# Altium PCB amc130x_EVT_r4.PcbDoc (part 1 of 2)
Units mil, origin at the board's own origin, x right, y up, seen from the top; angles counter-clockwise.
Board outline 4400 x 2100 mil, 2 copper layers (Top Layer, Bottom Layer), stack 62 mil thick; 70 components, 42 nets, 166 pads, 13 vias.
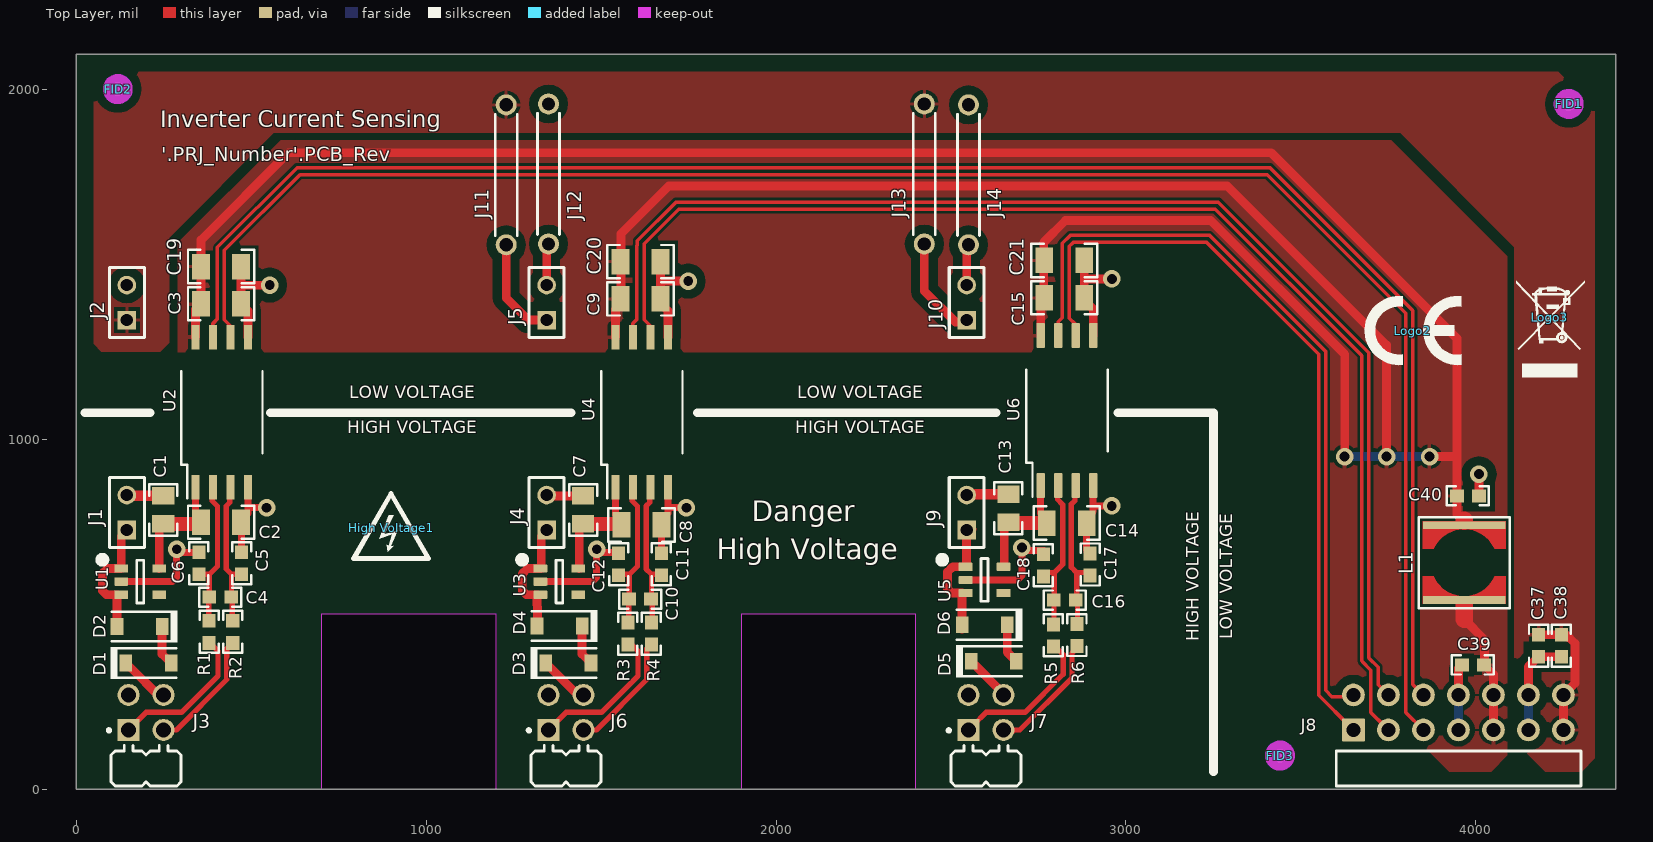
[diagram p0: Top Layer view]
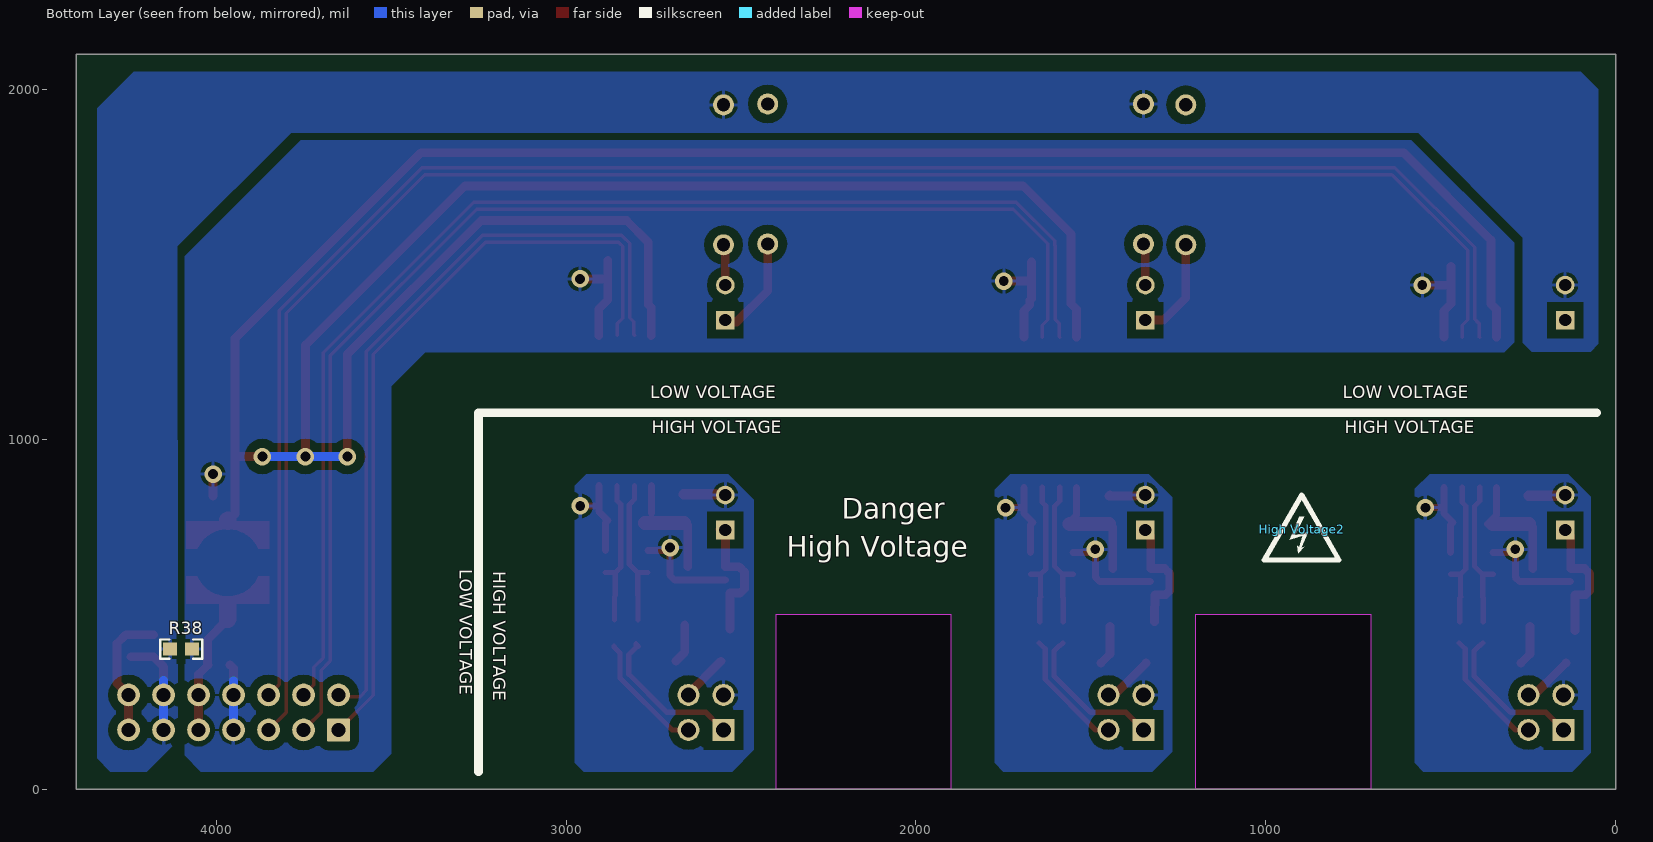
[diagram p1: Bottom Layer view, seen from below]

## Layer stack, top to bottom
Top Solder: solder mask 0.4, Solder Resist, Dk 3.5
Top Layer: signal copper 1.4
Dielectric1: core 59.2, FR-4, Dk 4.8
Bottom Layer: signal copper 1.4
Bottom Solder: solder mask 0.4, Solder Resist, Dk 3.5

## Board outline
0,0 0,2100 4400,2100 4400,0
cut-out: 1900,500 1900,0 2400,0 2400,500
cut-out: 700,500 700,0 1200,0 1200,500

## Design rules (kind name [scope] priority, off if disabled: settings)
AcuteAngle [All] p1: minimum=4.50000000000000E+0001 checktracksonly=FALSE
AssemblyTestPointUsage [All] p1: valid=2
BoardOutlineClearance BoardOutlineClearance_MountingHoles [OnCopper and InComponentClass('Mounting Holes')] p1: gap=39.37 ignorepadtopadclearanceinfootprint=FALSE
BoardOutlineClearance BoardOutlineClearance_Poly [OnCopper and IsPoly] p2: gap=25 ignorepadtopadclearanceinfootprint=FALSE
BoardOutlineClearance [OnCopper and Not InComponentClass('Logo') and not InComponentClass('FiducialMark') and not InRegion(1000,500,4000,800) and not InPoly and Not IsKeepOut] p3: gap=60 ignorepadtopadclearanceinfootprint=FALSE except(25: Poly-CutoutEdge Text-CutoutEdge; 50: Arc-CutoutEdge Track-CutoutEdge SMDPad-CutoutEdge THPad-CutoutEdge Via-CutoutEdge Fill-CutoutEdge Region-CutoutEdge)
Clearance Clearance_Keepouts [((IsTrack Or IsArc) And Not InPoly) And IsFree and IsKeepOut vs ((IsTrack Or IsArc) And Not InPoly) And IsFree and IsKeepOut] p1: gap=0 ignorepadtopadclearanceinfootprint=FALSE
Clearance Clearance_Small_Vias [(HoleDiameter = 10)] p2: gap=8 ignorepadtopadclearanceinfootprint=TRUE
Clearance Clearance_TP_blue_wires [HasFootprint('TP_H045P075')] p3: gap=15 ignorepadtopadclearanceinfootprint=TRUE
Clearance Clearance_3V3 [InNet('3V3')] p4: gap=15 ignorepadtopadclearanceinfootprint=TRUE
Clearance Clearance_10_mil_traces [Width = 10] p5: gap=8 ignorepadtopadclearanceinfootprint=TRUE
Clearance Clearance_Poly [InPolygon] p6: gap=25 ignorepadtopadclearanceinfootprint=TRUE except(10: Fill-Fill Fill-Poly Fill-Region Poly-Poly Poly-Region Region-Region)
Clearance Clearance_FiducialMark [IsKeepOut and InComponentClass('FiducialMark') vs IsPad and InComponentClass('FiducialMark')] p7: gap=0 ignorepadtopadclearanceinfootprint=FALSE
Clearance [All] p8: gap=7.87 ignorepadtopadclearanceinfootprint=TRUE
ComponentClearance ComponentClearance_MountingHoles_FiducialMarks [InComponentClass('Mounting Holes') vs InComponentClass('FiducialMark')] p1: gap=50 collisioncheckmode=3 verticalgap=10 showdistances=FALSE
ComponentClearance ComponentClearance_Shunt [InComponentClass('Header') vs InComponentClass('Shunt')] p2: gap=0 collisioncheckmode=3 verticalgap=0 showdistances=FALSE
ComponentClearance ComponentClearance_Logo [InComponentClass('Logo')] p3: gap=50 collisioncheckmode=3 verticalgap=10 showdistances=FALSE
ComponentClearance ComponentClearance_ScrewToNut [(HasFootprint('NY PMS 440 0025 PH')) vs (HasFootprint('Keystone_1902C'))] p4: gap=5 collisioncheckmode=3 verticalgap=10 showdistances=FALSE
ComponentClearance ComponentClearance_MountingHoles [InComponentClass('Mounting Holes')] p5: gap=250 collisioncheckmode=3 verticalgap=100000 showdistances=FALSE
ComponentClearance ComponentClearance_SmallPassives [HasFootprint('0201*') or HasFootprint('0402*') or HasFootprint('0508') or HasFootprint('0603*') or HasFootprint('0612') or HasFootprint('0805*') or HasFootprint('0815*') or HasFootprint('0830*') or HasFootprint('1206*') or HasFootprint('1210*') or HasFootprint('1808*') or HasFootprint('1812*') or HasFootprint('1825*') or HasFootprint('2010*') or HasFootprint('2220*') or HasFootprint('2225*') or HasFootprint('2512*') or HasFootprint('2728*') or HasFootprint('3518*') vs HasFootprint('0201*') or HasFootprint('0402*') or HasFootprint('0508') or HasFootprint('0603*') or HasFootprint('0612') or HasFootprint('0805*') or HasFootprint('0815*') or HasFootprint('0830*') or HasFootprint('1206*') or HasFootprint('1210*') or HasFootprint('1808*') or HasFootprint('1812*') or HasFootprint('1825*') or HasFootprint('2010*') or HasFootprint('2220*') or HasFootprint('2225*') or HasFootprint('2512*') or HasFootprint('2728*') or HasFootprint('3518*')] p6: gap=14.96 collisioncheckmode=3 verticalgap=10 showdistances=FALSE
ComponentClearance ComponentClearance_THtoSMT [IsThruComponent vs IsSMTComponent] p7: gap=20 collisioncheckmode=3 verticalgap=30 showdistances=FALSE
ComponentClearance ComponentClearance_TestPoint [HasFootprint('TP_H045P075')] p8: gap=0 collisioncheckmode=3 verticalgap=30 showdistances=FALSE
ComponentClearance ComponentClearance_THtoTH [IsThruComponent vs IsThruComponent] p9: gap=30 collisioncheckmode=3 verticalgap=30 showdistances=FALSE
ComponentClearance [All] p10: gap=30 collisioncheckmode=3 verticalgap=10 showdistances=FALSE
DiffPairsRouting [All] p1: maxlimit=100 minlimit=10 mostfreqgap=10 toplayer_minwidth=10 toplayer_maxwidth=15 toplayer_prefwidth=10 bottomlayer_minwidth=10 bottomlayer_maxwidth=15 bottomlayer_prefwidth=10 maxuncoupledlength=1000
FabricationTestPointUsage TestPointUsage [All] p1: valid=2 allowmultiple=FALSE
FabricationTestpoint Testpoint [All] p1: side=3 testpointundercomponent=TRUE minsize=40 maxsize=100 preferedsize=60 minholesize=0 maxholesize=40 preferedholesize=32 testpointgrid=1 allowsidetop=TRUE allowsidebottom=TRUE usegrid=TRUE gridtolerance=0.01
FanoutControl Fanout_LCC [IsLCC] p1: bgadir=Out bgaviamode=Centered fanoutstyle=Auto fanoutdirection=Alternating viagrid=1 // Fanout_LCC (Default Rule)
FanoutControl Fanout_BGA [IsBGA] p2: bgadir=Out bgaviamode=Centered fanoutstyle=Auto fanoutdirection=Alternating viagrid=1 // Fanout_BGA (Default Rule)
FanoutControl Fanout_Default [All] p4: bgadir=Out bgaviamode=Centered fanoutstyle=Auto fanoutdirection=Alternating viagrid=1 // Fanout_Default (Default Rule)
FanoutControl Fanout_Small [(CompPinCount < 5)] p5: bgadir=Out bgaviamode=Centered fanoutstyle=Auto fanoutdirection=OutThenIn viagrid=1 // Fanout_Small (Default Rule)
HoleSize [All] p1: absolutevalues=TRUE maxlimit=251 minlimit=7.87 maxpercent=80.000 minpercent=20.000
MinimumAnnularRing MinimumAnnularRing_ThermalPadVias [IsVia and InAnyComponent] p1: minimumring=5.91
MinimumAnnularRing [All] p2: minimumring=6
MinimumSolderMaskSliver MinimumSolderMaskSliver_Logo [InComponentClass('Logo') vs InComponentClass('Logo')] p1: minsoldermaskwidth=0.7
MinimumSolderMaskSliver [All] p2: minsoldermaskwidth=3.94
PlaneConnect [All] p1: planeconnectstyle=Relief reliefexpansion=10 reliefentries=4 reliefconductorwidth=10 reliefairgap=10
PolygonConnect [All] p1: connectstyle=Relief reliefconductorwidth=10 reliefentries=4 polygonreliefangle="90 Angle" airgapwidth=10
RoomDefinition Hardware [InComponentClass('Hardware')] p1: confinementstyle=ConfineIn formatcopy=TRUE lockcomponents=FALSE outline 8,-284 608,-284 608,1566 8,1566
RoutingVias ThermalPadVias [IsVia and InAnyComponent] p1: holewidth=7.87 width=19.68 viastyle="Through Hole" minholewidth=7.87 minwidth=19.68 maxholewidth=12.99 maxwidth=23.62
RoutingVias [All] p2: holewidth=16 width=34 viastyle="Through Hole" minholewidth=7.87 minwidth=22 maxholewidth=40 maxwidth=65
SilkToBoardRegionClearance [Not ((IsComment or IsDesignator) And (Hide <> 'False')) and not InRegion(1000,500,4000,800)] p1:
SilkToSilkClearance SilkToSilkClearance_Pb-FreeLogo [(HasFootprint('Pb-Free_Overlay_Medium') OR HasFootprint('Pb-Free_Overlay_Small')) vs (HasFootprint('Pb-Free_Overlay_Medium') OR HasFootprint('Pb-Free_Overlay_Small'))] p1: silktosilkclearance=0
SilkToSilkClearance [All] p2: silktosilkclearance=3.94
SilkToSolderMaskClearance SilkToComponentPadClearance [(IsPad or IsFill or IsRegion) and InAnycomponent] p1: minsilkscreentomaskgap=5 clearancetoexposedcopper=TRUE
SilkToSolderMaskClearance "Silk to Solder Mask Opening" [All] p2: minsilkscreentomaskgap=3 clearancetoexposedcopper=FALSE
SolderMaskExpansion [All] p1: expansion=1.97
UnRoutedNet [All] p1: checkbadconnections=TRUE
Width [All] p1: maxlimit=100 minlimit=6 preferedwidth=10 checkconnectedcopper=TRUE
14 further rules are at their usual default settings.

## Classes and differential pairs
component class FiducialMark: FID1 FID2 FID3
component class AssemblyNote: ZZ1 ZZ2 ZZ3 ZZ4
component class Header: J3 J6 J7 J8
differential pair Ics: +Ics_P -Ics_N
differential pair Ibs: +Ibs_P -Ibs_N
differential pair Ias: +Ias_P -Ias_N
differential pair Ic: +Ic_P -Ic_N
differential pair Ib: +Ib_P -Ib_N
differential pair Ia: +Ia_P -Ia_N

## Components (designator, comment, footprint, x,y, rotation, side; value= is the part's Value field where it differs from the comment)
C1 "GRM21BR70J106KE76L" 0805_HV 249.02,797.47 r270 top value=10uF
C2 "1206YC104KAT2A" 1206 414.24,762.33 r0 top value=0.1uF
C3 "1206YC104KAT2A" 1206 414.24,1386.56 r180 top value=0.1uF
C4 "06035A331JAT2A" 0603 411.82,548.34 r0 top value=330pF
C5 "06035A100JAT2A" 0603 472.85,644.98 r90 top value=10pF
C6 "06035A100JAT2A" 0603 350.66,644.98 r90 top value=10pF
C7 "GRM21BR70J106KE76L" 0805_HV 1449.02,797.47 r270 top value=10uF
C8 "1206YC104KAT2A" 1206 1615.76,754.71 r0 top value=0.1uF
C9 "1206YC104KAT2A" 1206 1612.73,1400.73 r180 top value=0.1uF
C10 "06035A331JAT2A" 0603 1611.49,542.39 r0 top value=330pF
C11 "06035A100JAT2A" 0603 1672.51,642.39 r90 top value=10pF
C12 "06035A100JAT2A" 0603 1550.46,642.39 r90 top value=10pF
C13 "GRM21BR70J106KE76L" 0805_HV 2664.02,802.47 r270 top value=10uF
C14 "1206YC104KAT2A" 1206 2830.76,759.71 r0 top value=0.1uF
C15 "1206YC104KAT2A" 1206 2823.69,1403.68 r180 top value=0.1uF
C16 "06035A331JAT2A" 0603 2824.95,540 r0 top value=330pF
C17 "06035A100JAT2A" 0603 2897.69,641.5 r90 top value=10pF
C18 "06035A100JAT2A" 0603 2764.1,639.04 r90 top value=10pF
C19 "GRM31MR71C225KA35L" 1206 414.24,1493.02 r180 top value=2.2uF
C20 "GRM31MR71C225KA35L" 1206 1612.73,1506.79 r180 top value=2.2uF
C21 "GRM31MR71C225KA35L" 1206 2823.69,1510.24 r180 top value=2.2uF
C37 "CGJ3E2X7R1C104K080AA" 0603 4178.99,409.45 r90 top value=0.1uF
C38 "GRM188R61C106KAALD" 0603 4243.99,409.45 r90 top value=10uF
C39 "CGJ3E2X7R1C104K080AA" 0603 3991.39,354.47 r0 top value=0.1uF
C40 "GRM188R61C106KAALD" 0603 3977.12,837.47 r180 top value=10uF
D1 "MMSZ4687-HE3-08" SOD-123 206.91,360 r0 top value=4.3V
D2 "MMSZ4687-HE3-08" SOD-123 181.22,464.58 r180 top value=4.3V
D3 "MMSZ4687-HE3-08" SOD-123 1406.82,360 r0 top value=4.3V
D4 "MMSZ4687-HE3-08" SOD-123 1381.41,465.71 r180 top value=4.3V
D5 "MMSZ4687-HE3-08" SOD-123 2621.91,365 r0 top value=4.3V
D6 "MMSZ4687-HE3-08" SOD-123 2596.22,469.58 r180 top value=4.3V
FID1 "Fiducial" Fiducial10-20 4265,1957.5 r0 top
FID2 "Fiducial" Fiducial10-20 118.99,2000 r0 top
FID3 "Fiducial" Fiducial10-20 3440,95.47 r0 top
"High Voltage1" "DANGER HIGH VOLTAGE" IEC_HighVoltage_Small 900,746.58 r0 top
"High Voltage2" "DANGER HIGH VOLTAGE" IEC_HighVoltage_Small 898,742.64 r180 bottom
J1 "5-534206-1" CONN_534206-1 145,790 r90 top
J2 "5-534206-1" CONN_534206-1 145,1390 r90 top
J3 "PBC02DBAN" Sullins_PxC02DBAN 200,218.78 r90 top
J4 "5-534206-1" CONN_534206-1 1344.63,790 r90 top
J5 "5-534206-1" CONN_534206-1 1344.63,1390 r90 top
J6 "PBC02DBAN" Sullins_PxC02DBAN 1400,218.78 r90 top
J7 "PBC02DBAN" Sullins_PxC02DBAN 2600,218.78 r90 top
J8 "TSW-107-08-G-D-RA" TSW-107-08-G-D-RA 3950,218.78 r0 top
J9 "5-534206-1" CONN_534206-1 2545,790 r90 top
J10 "5-534206-1" CONN_534206-1 2545,1390 r90 top
J11 "923345-04-C" 3M_923345-04-C 1229.02,1755 r90 top
J12 "923345-04-C" 3M_923345-04-C 1350.04,1757.5 r90 top
J13 "923345-04-C" 3M_923345-04-C 2423.85,1757.5 r90 top
J14 "923345-04-C" 3M_923345-04-C 2550,1755 r90 top
L1 "MSS6122-104MLB" MSS6122 3966.43,646.79 r90 top value=100uH
Logo2 "CE Mark" CE_Mark_5mm 3820,1310 r0 top
Logo3 "WEEE logo" WEEE_Minimum 4211.13,1348.19 r0 top
R1 "MCR03EZPJ000" 0603 380.36,449.06 r90 top value=0
R2 "MCR03EZPJ000" 0603 447.62,449.06 r90 top value=0
R3 "MCR03EZPJ000" 0603 1576.56,444.06 r90 top value=0
R4 "MCR03EZPJ000" 0603 1643.73,444.06 r90 top value=0
R5 "MCR03EZPJ000" 0603 2792.64,438.94 r90 top value=0
R6 "MCR03EZPJ000" 0603 2860,439.98 r90 top value=0
R38 "ERJ-3GEY0R00V" 0603 4100,400 r180 bottom value=0
U1 "TPS76350DBVT" DBV0005A_N 183.33,592.6 r0 top
U2 "AMC1301DWVR" DWV0008A 416.45,1076.56 r90 top
U3 "TPS76350DBVT" DBV0005A_N 1380.87,592.6 r0 top
U4 "AMC1301DWVR" DWV0008A 1616.45,1076.56 r90 top
U5 "TPS76350DBVT" DBV0005A_N 2595.87,597.4 r0 top
U6 "AMC1301DWVR" DWV0008A 2831.45,1081.56 r90 top
ZZ1 "This Assembly Note is for PCB labels only" AssemblyNoteLabel 5384,3683 r180 top
ZZ2 "These assemblies are ESD sensitive, ESD precautions shall be observed." AssemblyNote 2884,3483 r180 top
ZZ3 "These assemblies must be clean and free from flux and all contaminants. Use of no clean flux is not acceptable." AssemblyNote 4459,3308 r180 top
ZZ4 "These assemblies must comply with workmanship standards IPC-A-610 Class 2, unless otherwise specified." AssemblyNote 4134,3133 r180 top

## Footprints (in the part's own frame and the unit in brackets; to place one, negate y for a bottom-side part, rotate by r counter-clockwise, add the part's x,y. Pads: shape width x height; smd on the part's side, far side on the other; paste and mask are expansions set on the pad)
3M_923345-04-C [mil] "Jumper Wire, 400 mil Spacing, Yellow, Pkg of 200"
  round 60 hole 38: 1(-200,0) 2(200,0)
  silkscreen extent -173,-31 173,31, body extent -215,-30 215,30, height 80
0603 [mm] "0603 from SM-752 data"
  rect 1x0.95 smd: 1(-0.8,0) 2(0.8,0)
  silkscreen extent -1.52,-0.69 1.52,0.69, body extent -0.87,-0.47 0.87,0.47, height 1
0805_HV [mil] "0805 with 30mil clearance between pads"
  rect 50x63 smd: 1(-40,0) 2(40,0)
  silkscreen extent -74,-40 74,40, body extent -43,-29 43,29, height 57
1206 [mm] "1206 from SM-752 data"
  rect 1.3x1.85 smd: 1(-1.45,0) 2(1.45,0)
  silkscreen extent -2.4,-1.21 2.4,1.21, body extent -1.7,-0.9 1.7,0.9, height 1.35
AssemblyNote [mil] "Assembly Note"
AssemblyNoteLabel [mil] "Assembly Note for PCB Labels"
CE_Mark_5mm [mil] "Minimum text height for CE Mark"
  silkscreen extent -138,-98 138,98
CONN_534206-1 [mm] "TE_CONNECTIVITY"
  rect 1.35x1.35 hole 0.89: 1(-1.27,0)
  round 1.35 hole 0.89: 2(1.27,0)
  silkscreen extent -3.68,-1.27 2.54,2.03, body extent -2.51,-1.27 2.51,1.27, height 8.65
DBV0005A_N [mm] "SOT23, 5-Leads, Body 2.9x1.6mm, Pitch 0.95mm, Lead Span 2.8mm, IPC Medium Density"
  rrect17% 1x0.6 smd: 1(-1.375,0.95) 2(-1.375,0) 3(-1.375,-0.95) 4(1.375,-0.95) 5(1.375,0.95)
  silkscreen extent -0.25,-1.55 0.25,1.55, body extent -1.42,-1.46 1.42,1.46, height 1.09
DWV0008A [mm] "SOIC, 8-Leads, Body 5.95x7.6mm (max), Pitch 1.27mm"
  rrect17% 1.8x0.6 smd: 1(-5.45,1.905) 2(-5.45,0.635) 3(-5.45,-0.635) 4(-5.45,-1.905) 5(5.45,-1.905) 6(5.45,-0.635) 7(5.45,0.635) 8(5.45,1.905)
  silkscreen extent -6.25,-2.95 2.98,2.95, body extent -5.77,-2.92 5.77,2.93, height 2.67
Fiducial10-20 [mm]
  round 1 smd mask+0.5: 1(0,0)
  Top Layer keep-out circle w1.178: c0,0 r0.5
IEC_HighVoltage_Small [mil]
  silkscreen extent -107,-88 107,97
MSS6122 [mm] "Coilcraft recommended land pattern Document 640-1 Revised 04/16/10"
  rect 0.575x6 smd: 1(-2.712,0) 2(2.712,0)
  Top Layer region: 1,-3 1,-2.209 1.874,-1.539 2.362,-0.551 2.362,0.551 1.874,1.539 1,2.209 1,2.209 1,3 3,3 3,-3
  Top Layer region: -3,-3 -1,-3 -1,-2.209 -1.874,-1.539 -2.362,-0.551 -2.362,0.551 -1.874,1.539 -1,2.209 -1,2.209 -1,3 -3,3
  silkscreen extent -3.3,-3.3 3.3,3.3, body extent -2.97,-3 3,3, height 2.22
SOD-123 [mm] "On Semi recommended land pattern"
  rect 0.915x1.22 smd: 1(-1.637,0) 2(1.637,0)
  silkscreen extent -2.74,-1.17 2.03,1.17, body extent -1.93,-0.9 1.93,0.9, height 1.35
Sullins_PxC02DBAN [mm] "Header, 2.54mm, 2x2, R/A, TH"
  rect 1.6x1.6 hole 1.1: 1(-1.27,1.27)
  round 1.6 hole 1.1: 2(1.27,1.27) 3(-1.27,-1.27) 4(1.27,-1.27)
  silkscreen extent -5.33,-2.54 -1.2,2.8, body extent -11.17,-2.54 1.59,2.54, height 5.08
TSW-107-08-G-D-RA [mm] "Samtec Right Angle Header"
  rrect6% 1.65x1.65 hole 1: 1(-7.62,-1.27)
  round 1.65 hole 1: 2(-7.62,1.27) 3(-5.08,-1.27) 4(-5.08,1.27) 5(-2.54,-1.27) 6(-2.54,1.27) 7(0,-1.27) 8(0,1.27) 9(2.54,-1.27) 10(2.54,1.27) 11(5.08,-1.27) 12(5.08,1.27) 13(7.62,-1.27) 14(7.62,1.27)
  silkscreen extent -8.87,-5.33 8.89,-2.79, body extent -8.89,-11.18 8.89,1.59, height 5.56
WEEE_Minimum [mil] "WEEElie bin"
  silkscreen extent -95,-172 99,104

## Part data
C1 C7 C13: library part CMP-0008311-2, "CAP, CERM, 10 uF, 6.3 V, +/- 10%, X7R, 0805", Cap_Case=0805, Manufacturer=MuRata, Supplier Part Number 1=490-3904-1-ND, TempCo=X7R, Tolerance_%=10%, Value1=Unknown, Value2=6.3V, ValueDisplayed=10uF
C2 C3 C8 C9 C14 C15: library part CMP-0860522-1, "CAP, CERM, 0.1 µF, 16 V,+/- 10%, X7R, 1206", Cap_Case=1206, Manufacturer=AVX, TempCo=X7R, Tolerance_%=10%, Value2=16V, ValueDisplayed=0.1µF
C4 C10 C16: library part CMP-0006784-4, "CAP, CERM, 330 pF, 50 V, +/- 5%, C0G/NP0, 0603", Cap_Case=0603, Manufacturer=AVX, Supplier Part Number 1=478-1181-1-ND, TempCo=C0G/NP0, Tolerance_%=5%, Value1="0.071 ohm", Value2=50V, ValueDisplayed=330pF
C5 C6 C11 C12 C17 C18: library part CMP-0006761-4, "CAP, CERM, 10 pF, 50 V, +/- 5%, C0G/NP0, 0603", Cap_Case=0603, Manufacturer=AVX, Supplier Part Number 1=478-1163-1-ND, TempCo=C0G/NP0, Tolerance_%=5%, Value1="0.403 ohm", Value2=50V, ValueDisplayed=10pF
C19 C20 C21: library part CMP-0008987-1, "CAP, CERM, 2.2 uF, 16 V, +/- 10%, X7R, 1206", Cap_Case=1206, Manufacturer=MuRata, Supplier Part Number 1=81-GRM426X225K16L, TempCo=X7R, Tolerance_%=10%, Value1="0.006 ohm", Value2=16V, ValueDisplayed=2.2uF
C37 C39: library part CMP-0007106-4, "CAP, CERM, 0.1 uF, 16 V, +/- 10%, X7R, AEC-Q200 Grade 1, 0603", Cap_Case=0603, Manufacturer=TDK, Supplier Part Number 1=445-8136-1-ND, TempCo=X7R, Tolerance_%=10%, Value1=Unknown, Value2=16V, ValueDisplayed=0.1uF
C38 C40: library part CMP-0086225-1, "CAP, CERM, 10 µF, 16 V,+/- 10%, X5R, 0603", Cap_Case=0603, Manufacturer=MuRata, Supplier Part Number 1=490-10728-1-ND, TempCo=X5R, Tolerance_%=10%, Value2=16V, ValueDisplayed=10µF
D1 D2 D3 D4 D5 D6: library part CMP-0077560-1, "Diode, Zener, 4.3 V, 500 mW, AEC-Q101, SOD-123", Manufacturer=Vishay-Semiconductor, Power_W=500mW, Supplier Part Number 1=MMSZ4687-HE3-08-ND, Value1=0.5W
FID1 FID2 FID3: library part CMP-0077181-1, "Fiducial mark.  There is nothing to buy or mount.", Manufacturer=N/A
"High Voltage1" "High Voltage2": library part CMP-0074835-1, "IEC 61010-1 High Voltage Warning"
J1 J2 J4 J5 J9 J10: library part CMP-0054836-1, "Connector, Receptacle, 100mil, 2x1, Gold plated, TH", Manufacturer="TE Connectivity", Supplier Part Number 1=A32932-ND
J3 J6 J7: library part CMP-0054605-1, "Header, 2.54mm, 2x2, Gold, R/A, TH", Color=Black, Current_A=3A, Manufacturer="Sullins Connector Solutions", Supplier Part Number 1=S2111E-02-ND, Voltage_V=1.8kV
J8: library part CMP-0075417-2, "Header, 100mil, 7x2, Gold, R/A, TH", Color=Black, Current_A=6.3A, Manufacturer=Samtec, Supplier Part Number 1=SAM1037-07-ND, Voltage_V=550V
J11 J12 J13 J14: library part CMP-0075057-1, "Jumper Wire, 400 mil Spacing, Yellow, Pkg of 200", Manufacturer=3M, Supplier Part Number 1=923345-04-ND
L1: library part CMP-0061563-2, "Inductor, Shielded Drum Core, Ferrite, 100 uH, 0.4 A, 1.37 ohm, SMD", Manufacturer=Coilcraft, Value1="1.37 ohm", Value2=0.4A, ValueDisplayed=100uH
Logo2: library part CMP-0074844-1
Logo3: library part CMP-0074769-1
R1 R2 R3 R4 R5 R6: library part CMP-0025883-3, "RES, 0, 5%, 0.1 W, 0603", Manufacturer=Rohm, Power_W=100mW, Supplier Part Number 1=RHM0.0GCT-ND, TempCo="400 ppm/C", Tolerance_%=5%, Value2=0.1W, Value_Code=0000, ValueDisplayed=0
R38: library part CMP-0025874-1, "RES, 0, 5%, 0.1 W, 0603", Manufacturer=Panasonic, Power_W=100mW, Supplier Part Number 1=P0.0GCT-ND, TempCo="600 ppm/C", Tolerance_%=5%, Value2=0.1W, Value_Code=0000, ValueDisplayed=0
U1 U3 U5: library part CMP-0035557-1, "Single Output LDO, 150 mA, Fixed 5 V Output, 2.7 to 10 V Input, with Low IQ, 5-pin SOT-23 (DBV), -40 to 125 degC, Green (RoHS & no Sb/Br)", Manufacturer="Texas Instruments"
U2 U4 U6: library part CMP-0075815-1, "Precision +/-250-mV Input, 3-us Delay, Reinforced Isolated Amplifier, DWV0008A (SOIC-8)", Alternate Manufacturer="Texas Instruments", Alternate PartNumber=AMC1301DWV
ZZ1: library part CMP-0003616-3
ZZ2: library part CMP-0077236-1
ZZ3: library part CMP-0077237-1
ZZ4: library part CMP-0077238-1

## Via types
v1: diameter 50, hole 28, Top Layer to Bottom Layer, 13 vias

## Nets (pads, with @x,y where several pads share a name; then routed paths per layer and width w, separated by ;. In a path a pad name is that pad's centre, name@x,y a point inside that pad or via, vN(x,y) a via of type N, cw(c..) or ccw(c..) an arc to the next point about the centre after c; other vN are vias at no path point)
3V3: C39.2 J8.9 J8.10 L1.1 | length 408.3
  Top Layer w25: 3966.43,485 4024.61,426.82 4024.61,356.19 C39.2@4022.88,354.47 4050,327.35 4050,253.45 J8.9@4050,153.45
  Top Layer w50: 3966.43,485 3966.43,525.68
3V3f: C3.2 C9.2 C15.2 C19.2 C20.2 C21.2 C40.2 L1.2 U2.8 U4.8 U6.8 | length 9709.2
  Top Layer w25: U2.8@341.45,1291.13 341.45,1370.85 C3.2@357.16,1386.56 C19.2@357.16,1493.02 357.16,1568.58 606.67,1818.09 3415.18,1818.09 3945.62,1287.66 3945.62,950 ; U4.8@1541.45,1291.13 1541.45,1370.85 1557.16,1386.56 1557.16,1586.4 1693.98,1723.22 3289.78,1723.22 3744.56,1268.44 v1(3744.56,950) ; U6.8@2756.45,1296.13 2756.45,1375.85 2764.96,1384.36 2764.96,1562.13 2827.44,1624.61 3242.12,1624.61 3624.83,1241.9 v1(3624.83,950) ; v1(3867.74,950) 3945.62,950 ; L1.2@3966.43,764.79 3945.62,785.6 C40.2@3945.62,837.47 3945.62,950
  Top Layer w50: L1.2@3966.43,764.79 3966.43,767.9
  Bottom Layer w25: v1(3624.83,950) v1(3744.56,950) v1(3867.74,950)
5V: C37.2 C38.2 J2.1 J8.13 J8.14 J11.2 J13.2 | length 390.6
  Top Layer w25: C37.2@4178.99,440.94 C38.2@4243.99,440.94 4258.11,440.94 4283.07,415.98 4283.07,301.85 J8.14@4250,268.78 J8.13@4250,168.78 J8.13@4250,153.45
5V_GND: C37.1 C38.1 J2.2 J8.11 J8.12 J12.2 J14.2 R38.1 | length 358.1
  Top Layer w25: J8.12@4150,253.45 4150,348.96 C37.1@4178.99,377.95 C38.1@4243.99,377.95
  Bottom Layer w25: J8.11@4150,153.45 4150,253.45 4150,310
5VisoA: C1.2 C2.1 U1.5 U2.1 | length 351.4
  Top Layer w20: U2.1@341.45,862 341.45,782.96 C2.1@359.62,764.79 ; C2.1@352.3,757.47 C2.1@359.62,764.79 ; C2.1@357.16,762.33 C2.1@359.62,764.79 ; C2.1@366.94,757.47 C2.1@359.62,764.79
  Top Layer w25: U1.5@237.46,630 C1.2@237.46,749.24
  Top Layer w40: C1.2@249.02,757.47 C2.1@352.3,757.47
5VisoB: C7.2 C8.1 U3.5 U4.1 | length 356.1
  Top Layer w20: U4.1@1541.45,862 1541.45,782.96 1566.94,757.47 1561.43,757.47 C8.1@1558.67,754.71
  Top Layer w25: U3.5@1437.46,630 C7.2@1437.46,749.24
  Top Layer w40: C7.2@1449.02,757.47 C8.1@1561.43,757.47
5VisoC: C13.2 C14.1 U5.5 U6.1 | length 315.7
  Top Layer w20: C13.2@2663.45,759.71 2660.69,762.47 C13.2@2664.02,762.47 ; C14.1@2756.45,787.96 U6.1@2756.45,867
  Top Layer w25: U5.5@2652.46,635 C13.2@2652.46,754.24
  Top Layer w40: C13.2@2663.45,759.71 C14.1@2773.67,759.71
DGND: C3.1 C9.1 C15.1 C19.1 C20.1 C21.1 C39.1 C40.1 J8.7 J8.8 R38.2 U2.5 U4.5 U6.5 | length 1227
  Top Layer w25: C19.1@471.33,1493.02 471.33,1439.79 ; U2.5@491.45,1291.13 491.45,1366.45 C3.1@471.33,1386.56 471.33,1439.79 ; v1(553.34,1440) 553.13,1439.79 471.33,1439.79 ; C20.1@1669.82,1506.79 1669.82,1453.76 ; U4.5@1691.45,1291.13 1691.45,1366.45 1674.82,1383.08 1674.82,1395.73 C9.1@1669.82,1400.73 1669.82,1453.76 ; v1(1749.21,1451.32) 1672.25,1451.32 1669.82,1453.76 ; C21.1@2880.78,1510.24 2880.78,1462.6 ; U6.5@2906.45,1296.13 2906.45,1371.45 2880.78,1397.11 C15.1@2880.78,1403.68 2880.78,1462.6 ; v1(2960,1457.42) 2885.96,1457.42 2880.78,1462.6 ; J8.8@3950,253.45 3950,344.58 C39.1@3959.89,354.47 ; C40.1@4008.61,837.47 v1(4008.61,899.91)
  Bottom Layer w25: J8.7@3950,153.45 3950,253.45 3950,309.45
Ia_N: J8.5 U2.6 | length 5111.5
  Top Layer w10: U2.6@439.21,1291.13 439.21,1324.87 423.46,1340.62 423.46,1539.34 639.84,1755.72 3403.31,1755.72 3800,1359.03 3800,218.78 J8.5@3850,168.78 J8.5@3850,153.45
Ia_P: J8.6 U2.7 | length 5068.9
  Top Layer w10: U2.7@389.21,1291.13 391.03,1292.96 391.03,1330.15 402.75,1341.86 402.75,1436.79 403.46,1437.5 403.46,1547.62 631.55,1775.72 3411.59,1775.72 3820,1367.32 3820,298.78 J8.6@3850,268.78 J8.6@3850,253.45
Ias_N: J3.3 R2.1 | length 360.4
  Top Layer w15: J3.3@250,148.78 270,168.78 286.65,168.78 430.52,312.65 430.52,400.47 R2.1@447.62,417.56
Ias_P: J3.1 R1.1 | length 445.4
  Top Layer w15: J3.1@150,148.78 J3.1@150,168.78 200.22,219 301.52,219 405.52,323.01 405.52,394.08 389.54,410.06 387.86,410.06 R1.1@380.36,417.56
Ib_N: J8.3 U4.6 | length 3641.1
  Top Layer w10: U4.6@1639.21,1291.13 1639.21,1324.87 1623.46,1340.62 1623.46,1558.08 1722.48,1657.11 3255.58,1657.11 3674.12,1238.57 3674.12,366.12 3675,365.24 3675,364.47 3700,339.47 3700,218.78 3741.7,177.09 J8.3@3741.7,164.02
Ib_P: J8.4 U4.7 | length 3598.4
  Top Layer w10: U4.7@1589.21,1291.13 1591.03,1292.96 1591.03,1330.15 1602.75,1341.86 1602.75,1552.54 1603.46,1553.25 1603.46,1566.37 1714.2,1677.11 3263.87,1677.11 3694.12,1246.85 3694.12,374.4 3721.01,347.51 3721.01,297.77 3741.7,277.09 J8.4@3741.7,264.02
Ibs_N: J6.3 R4.1 | length 360.4
  Top Layer w15: J6.3@1450,148.78 1470,168.78 1486.66,168.78 1630.52,312.65 1630.52,400.47 R4.1@1647.62,417.56
Ibs_P: J6.1 R3.1 | length 445.4
  Top Layer w15: J6.1@1350,148.78 J6.1@1350,168.78 1400.22,219 1501.52,219 1605.52,323.01 1605.52,394.08 1589.54,410.06 1587.86,410.06 R3.1@1580.36,417.56
Ic_N: J8.1 U6.6 | length 2226.1
  Top Layer w10: U6.6@2854.21,1296.13 2854.21,1329.87 2838.46,1345.62 2838.46,1551.17 2848.94,1561.65 3230.83,1561.65 3550.48,1242 3550.48,268.3 3641.7,177.09 J8.1@3641.7,164.02
Ic_P: J8.2 U6.7 | length 2214.8
  Top Layer w10: U6.7@2804.21,1296.13 2806.03,1297.96 2806.03,1335.15 2817.75,1346.86 2817.75,1458.34 2818.46,1459.05 2818.46,1559.46 2840.66,1581.65 3239.11,1581.65 3570.48,1250.29 3570.48,281.82 3588.28,264.02 J8.2@3641.7,264.02
Ics_N: J7.3 R6.1 | length 346.3
  Top Layer w15: J7.3@2665,153.78 2680,168.78 2696.66,168.78 2845.52,317.65 2845.52,388.7 2862.62,405.79 R6.1@2862.62,408.48
Ics_P: J7.1 R5.1 | length 451.5
  Top Layer w15: J7.1@2565,153.78 2565,183.78 2600.22,219 2711.52,219 2820.52,328.01 2820.52,384.48 2800.26,404.74 2800.26,415.06 R5.1@2792.64,407.44
isoGNDA: C1.1 C2.2 C5.2 C6.2 J1.2 J3.2 U1.2 U2.4 | length 668.7
  Top Layer w20: U1.2@129.19,592.6 275.12,592.6 287.52,605 v1(287.52,685) 288.41,685 296.93,676.48 C6.2@350.66,676.48 ; C5.2@472.85,676.48 472.85,754.71 465.78,761.78 491.45,787.45 491.45,803.72 ; U2.4@491.45,862 491.45,803.72 ; v1(544.21,803.77) 544.16,803.72 491.45,803.72
  Top Layer w30: J1.2@145,840 145.09,839.91 145.09,837.29 145.27,837.47 C1.1@249.02,837.47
